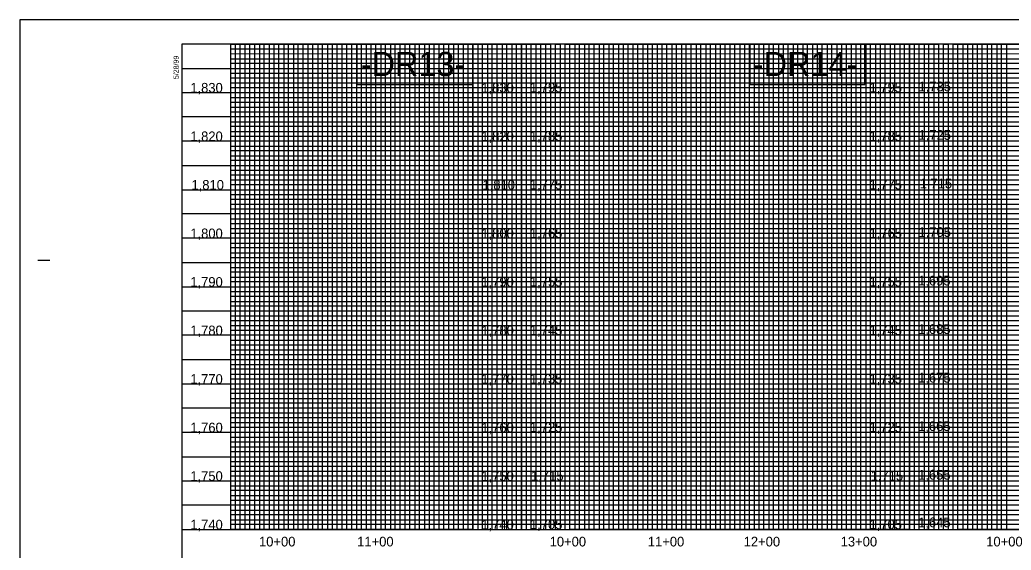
# Model space of a CAD drawing. Extents: x 505602 to 507286, y 483109 to 484209.
# Drawn here: x 505602 to 506624, y 483662 to 484209 of the extents above; entities that cross this region are included whole.
import ezdxf

# ---------------------------------------------------------------- set-up
doc = ezdxf.new("R2010")
doc.units = 0
for name, color, linetype in [('Exist Vertical Profile Vertical Axis Label', 7, 'Continuous'), ('Old_Level_1', 7, 'Continuous'), ('Prop Grid Mask', 7, 'Continuous'), ('Sheet Layout Profile Border Port 1', 7, 'Continuous'), ('Sheet Layout Profile Border Port 2', 7, 'Continuous'), ('Sheet Plot Border Outside CELL', 7, 'Continuous'), ('Sheet Profile CELL', 7, 'Continuous'), ('Sheet Profile Grid Major CELL', 7, 'Continuous'), ('Sheet Profile Grid Middle CELL', 7, 'Continuous'), ('Sheet Profile Grid Minor CELL', 7, 'Continuous')]:
    doc.layers.add(name, color=color, linetype=linetype)

msp = doc.modelspace()

# ---------------------------------------------------------------- linework, layer by layer
at = {"layer": 'Prop Grid Mask'}
for points in [[(506069.1, 484183.7), (505949.5, 484183.7), (505949.5, 484142), (506069.1, 484142)], [(506473.2, 484183.7), (506354.7, 484183.7), (506354.7, 484142), (506473.2, 484142)]]:
    msp.add_lwpolyline(points, close=True, dxfattribs=at)
at = {"layer": 'Sheet Layout Profile Border Port 1'}
msp.add_lwpolyline([(505819.5, 484183.7), (506069.1, 484183.7), (506069.1, 483683.7), (505819.5, 483683.7)], close=True, dxfattribs=at)
at = {"layer": 'Sheet Layout Profile Border Port 2'}
for points in [[(506169.1, 484183.7), (506519.1, 484183.7), (506519.1, 483683.7), (506169.1, 483683.7)], [(506569.1, 484183.7), (507069.1, 484183.7), (507069.1, 483683.7), (506569.1, 483683.7)]]:
    msp.add_lwpolyline(points, close=True, dxfattribs=at)
at = {"layer": 'Sheet Plot Border Outside CELL'}
msp.add_lwpolyline([(505602.1, 483108.7), (507286.1, 483108.7), (507286.1, 484208.7), (505602.1, 484208.7)], close=True, dxfattribs=at)
at = {"layer": 'Sheet Profile CELL'}
for p, q in [((506119.1, 483683.7), (506119.1, 484183.7)), ((506519.1, 483683.7), (506519.1, 484183.7)), ((505620.6, 483961.2), (505633.1, 483961.2)), ((505769.1, 483683.7), (507269.1, 483683.7))]:
    msp.add_line(p, q, dxfattribs=at)
msp.add_lwpolyline([(507269.1, 484183.7), (505769.1, 484183.7), (505769.1, 483133.7), (507269.1, 483133.7)], close=True, dxfattribs=at)
at = {"layer": 'Sheet Profile Grid Major CELL'}
for points in [[(505819.1, 484183.7), (505819.1, 483683.7), (505869.1, 483683.7), (505869.1, 484183.7), (505919.1, 484183.7), (505919.1, 483683.7), (505969.1, 483683.7), (505969.1, 484183.7), (506019.1, 484183.7), (506019.1, 483683.7), (506069.1, 483683.7), (506069.1, 484183.7), (506119.1, 484183.7), (506119.1, 483683.7), (506169.1, 483683.7), (506169.1, 484183.7), (506219.1, 484183.7), (506219.1, 483683.7), (506269.1, 483683.7), (506269.1, 484183.7), (506319.1, 484183.7), (506319.1, 483683.7), (506369.1, 483683.7), (506369.1, 484183.7), (506419.1, 484183.7), (506419.1, 483683.7), (506469.1, 483683.7), (506469.1, 484183.7), (506519.1, 484183.7), (506519.1, 483683.7), (506569.1, 483683.7), (506569.1, 484183.7), (506619.1, 484183.7), (506619.1, 483683.7), (506669.1, 483683.7)], [(505769.1, 484133.7), (507069.1, 484133.7)], [(507069.1, 484083.7), (505769.1, 484083.7), (505769.1, 484033.7), (507069.1, 484033.7)], [(507269.1, 483983.7), (505769.1, 483983.7), (505769.1, 483933.7), (507269.1, 483933.7)], [(507269.1, 483883.7), (505769.1, 483883.7), (505769.1, 483833.7), (507269.1, 483833.7)], [(507269.1, 483783.7), (505769.1, 483783.7), (505769.1, 483783.7), (505769.1, 483733.7), (507269.1, 483733.7)]]:
    msp.add_lwpolyline(points, dxfattribs=at)
at = {"layer": 'Sheet Profile Grid Middle CELL'}
msp.add_line((505769.1, 484158.7), (507069, 484158.7), dxfattribs=at)
msp.add_line((505769.1, 484158.7), (507069, 484158.7), dxfattribs=at)
for points in [[(505844.1, 484183.7), (505844.1, 483683.7), (505894.1, 483683.7), (505894.1, 484183.7), (505944.1, 484183.7), (505944.1, 483683.7), (505994.1, 483683.7), (505994.1, 484183.7), (506044.1, 484183.7), (506044.1, 483683.7), (506094.1, 483683.7), (506094.1, 484183.7), (506144.1, 484183.7), (506144.1, 483683.7), (506194.1, 483683.7), (506194.1, 484183.7), (506244.1, 484183.7), (506244.1, 483683.7), (506294.1, 483683.7), (506294.1, 484183.7), (506344.1, 484183.7), (506344.1, 483683.7), (506394.1, 483683.7), (506394.1, 483683.7), (506394.1, 484183.7), (506444.1, 484183.7), (506444.1, 483683.7), (506494.1, 483683.7), (506494.1, 484183.7), (506544.1, 484183.7), (506544.1, 483683.7), (506594.1, 483683.7), (506594.1, 484183.7), (506644.1, 484183.7)], [(507069.1, 484108.7), (505769.1, 484108.7), (505769.1, 484058.7), (507069.1, 484058.7)], [(507269.1, 484008.7), (505769.1, 484008.7), (505769.1, 483958.7), (507094.1, 483958.7)], [(507269.1, 483908.7), (505769.1, 483908.7), (505769.1, 483858.7), (507269.1, 483858.7)], [(507269.1, 483808.7), (505769.1, 483808.7), (505769.1, 483758.7), (507269.1, 483758.7)], [(507269.1, 483708.7), (505769.1, 483708.7)]]:
    msp.add_lwpolyline(points, dxfattribs=at)
at = {"layer": 'Sheet Profile Grid Minor CELL'}
for p, q in [((505819.1, 484178.7), (507069.1, 484178.7)), ((505819.1, 484173.7), (505819.1, 484173.7)), ((507069.1, 484173.7), (505819.1, 484173.4)), ((505819.1, 484168.7), (507069.1, 484168.7)), ((507069, 484048.7), (505819.1, 484048.7)), ((507069.1, 484043.7), (505819.1, 484043.7)), ((507069.1, 484038.7), (505819.1, 484038.7)), ((505819.1, 484028.7), (507069.1, 484028.7)), ((507069.1, 484023.7), (505819.1, 484023.7)), ((505819.1, 484018.7), (507219.1, 484018.7)), ((507219.1, 483998.7), (505819.1, 483998.7)), ((505819.1, 483993.7), (507219.1, 483993.7)), ((507219.1, 483973.7), (505819.1, 483973.7)), ((505819.1, 483968.7), (507219.1, 483968.7)), ((507219.1, 483948.7), (505819.1, 483948.7)), ((505819.1, 483943.7), (507219.1, 483943.7)), ((507219.1, 483938.7), (505819.1, 483938.7)), ((505819.1, 483928.7), (507219.1, 483928.7)), ((507219.1, 483923.7), (505819.1, 483923.7)), ((505819.1, 483918.7), (507219.1, 483918.7)), ((507219.1, 483913.7), (505819.1, 483913.7)), ((505819.1, 483903.7), (507219.1, 483903.7)), ((507219.1, 483898.7), (505819.1, 483898.7)), ((505819.1, 483893.7), (507219.1, 483893.7)), ((507219.1, 483888.7), (505819.1, 483888.7)), ((505819.1, 483878.7), (507219.1, 483878.7)), ((507219.1, 483873.7), (505819.1, 483873.7)), ((505819.1, 483868.7), (507219.1, 483868.7)), ((507219.1, 483863.7), (505819.1, 483863.7)), ((505819.1, 483853.7), (507219.1, 483853.7)), ((507219.1, 483848.7), (505819.1, 483848.7)), ((505819.1, 483843.7), (507219.1, 483843.7)), ((507219.1, 483838.7), (505819.1, 483838.7)), ((505819.1, 483828.7), (507219.1, 483828.7)), ((507219.1, 483823.7), (505819.1, 483823.7)), ((505819.1, 483818.7), (507219.1, 483818.7)), ((507219.1, 483813.7), (505819.1, 483813.7)), ((505819.1, 483803.7), (507219.1, 483803.7)), ((507219.1, 483798.7), (505819.1, 483798.7)), ((507219.1, 483793.7), (505819.1, 483793.7)), ((507219.1, 483788.7), (505819.1, 483788.7)), ((505819.1, 483778.7), (507219.1, 483778.7)), ((507219.1, 483773.7), (505819.1, 483773.7)), ((505819.1, 483768.7), (507219.1, 483768.7)), ((507219.1, 483763.7), (505819.1, 483763.7)), ((505819.1, 483753.7), (507219.1, 483753.7)), ((507219.1, 483748.7), (505819.1, 483748.7)), ((505819.1, 483743.7), (507219.1, 483743.7)), ((507219.1, 483738.7), (505819.1, 483738.7)), ((505819.1, 483728.7), (507219.1, 483728.7)), ((507219.1, 483723.7), (505819.1, 483723.7)), ((505819.1, 483718.7), (507219.1, 483718.7)), ((507219.1, 483713.7), (505819.1, 483713.7)), ((505819.1, 483703.7), (507219.1, 483703.7)), ((507219.1, 483698.7), (505819.1, 483698.7)), ((505819.1, 483693.7), (507219.1, 483693.7))]:
    msp.add_line(p, q, dxfattribs=at)
for points in [[(505824.1, 484183.7), (505824.1, 483683.7), (505829.1, 483683.7), (505829.1, 484183.7), (505834.1, 484183.7), (505834.1, 483683.7), (505839.1, 483683.7), (505839.1, 484183.7), (505849.1, 484183.7), (505849.1, 483683.7), (505854.1, 483683.7), (505854.1, 484183.7), (505859.1, 484183.7), (505859.1, 483683.7), (505864.1, 483683.7), (505874.1, 483683.7), (505879.1, 483683.7), (505879.1, 484183.7), (505884.1, 484183.7), (505884.1, 483683.7), (505889.1, 483683.7), (505889.1, 484183.7), (505899.1, 484183.7), (505899.1, 483683.7), (505904.1, 483683.7), (505904.1, 484183.7), (505909.1, 484183.7), (505909.1, 483683.7), (505914.1, 483683.7), (505914.1, 484183.7), (505924.1, 484183.7), (505924.1, 483683.7), (505929.1, 483683.7), (505929.1, 484183.7), (505934.1, 484183.7), (505934.1, 483683.7), (505939.1, 483683.7), (505939.1, 484183.7), (505949.1, 484183.7), (505949.1, 483683.7), (505954.1, 483683.7), (505954.1, 484183.7), (505959.1, 484183.7), (505959.1, 483683.7), (505964.1, 483683.7), (505964.1, 484183.7), (505974.1, 484183.7), (505974.1, 483683.7), (505979.1, 483683.7), (505979.1, 484183.7), (505984.1, 484183.7), (505984.1, 483683.7), (505989.1, 483683.7), (505989.1, 484183.7), (505999.1, 484183.7), (505999.1, 483683.7), (506004.1, 483683.7), (506004.1, 484183.7), (506009.1, 484183.7), (506009.1, 483683.7), (506014.1, 483683.7), (506014.1, 484183.7), (506024.1, 484183.7), (506024.1, 483683.7), (506029.1, 483683.7), (506029.1, 484183.7), (506034.1, 484183.7), (506034.1, 483683.7)], [(505864.1, 483683.7), (505864.1, 484183.7), (505874.1, 484183.7), (505874.1, 483683.7)], [(506034.1, 483683.7), (506039.1, 483683.7), (506039.1, 484183.7), (506049.1, 484183.7), (506049.1, 483683.7), (506054.1, 483683.7), (506054.1, 484183.7), (506059.1, 484183.7), (506059.1, 483683.7), (506064.1, 483683.7), (506064.1, 484183.7), (506074.1, 484183.7), (506074.1, 483683.7), (506079.1, 483683.7), (506079.1, 484183.7), (506084.1, 484183.7), (506084.1, 483683.7), (506089.1, 483683.7), (506089.1, 484183.7), (506099.1, 484183.7), (506099.1, 483683.7), (506104.1, 483683.7), (506104.1, 484183.7), (506109.1, 484183.7), (506109.1, 483683.7), (506114.1, 483683.7), (506114.1, 484183.7), (506124.1, 484183.7), (506124.1, 483683.7), (506129.1, 483683.7), (506129.1, 484183.7), (506134.1, 484183.7), (506134.1, 483683.7), (506139.1, 483683.7), (506139.1, 484183.7), (506149.1, 484183.7), (506149.1, 483683.7), (506154.1, 483683.7), (506154.1, 484183.7), (506159.1, 484183.7), (506159.1, 483683.7), (506164.1, 483683.7), (506164.1, 484183.7), (506174.1, 484183.7), (506174.1, 483683.7), (506179.1, 483683.7), (506179.1, 484183.7), (506184.1, 484183.7), (506184.1, 483683.7), (506189.1, 483683.7), (506189.1, 484183.7), (506199.1, 484183.7), (506199.1, 483683.7), (506204.1, 483683.7), (506204.1, 484183.7), (506209.1, 484183.7), (506209.1, 483683.7), (506214.1, 483683.7), (506214.1, 484183.7), (506224.1, 484183.7), (506224.1, 483683.7), (506229.1, 483683.7), (506229.1, 484183.7), (506234.1, 484183.7), (506234.1, 483683.7), (506239.1, 483683.7), (506239.1, 484183.7), (506249.1, 484183.7), (506249.1, 483683.7), (506254.1, 483683.7), (506254.1, 484183.7), (506259.1, 484183.7), (506259.1, 483683.7), (506264.1, 483683.7), (506264.1, 484183.7), (506274.1, 484183.7), (506274.1, 483683.7), (506279.1, 483683.7), (506279.1, 484183.7), (506284.1, 484183.7), (506284.1, 483683.7), (506289.1, 483683.7), (506289.1, 484183.7), (506299.1, 484183.7), (506299.1, 483683.7), (506304.1, 483683.7), (506304.1, 484183.7), (506309.1, 484183.7), (506309.1, 483683.7), (506314.1, 483683.7), (506314.1, 484183.7), (506324.1, 484183.7), (506324.1, 483683.7), (506329.1, 483683.7), (506329.1, 484183.7), (506334.1, 484183.7), (506334.1, 483683.7), (506339.1, 483683.7), (506339.1, 484183.7), (506349.1, 484183.7)], [(506349.1, 484183.7), (506349.1, 483683.7), (506354.1, 483683.7), (506354.1, 484183.7), (506359.1, 484183.7), (506359.1, 483683.7), (506364.1, 483683.7), (506364.1, 484183.7), (506374.1, 484183.7), (506374.1, 483683.7), (506379.1, 483683.7), (506379.1, 484183.7), (506384.1, 484183.7), (506384.1, 483683.7), (506389.1, 483683.7), (506389.1, 484183.7), (506399.1, 484183.7), (506399.1, 483683.7), (506404.1, 483683.7), (506404.1, 484183.7), (506409.1, 484183.7), (506409.1, 483683.7), (506414.1, 483683.7), (506414.1, 484183.7), (506424.1, 484183.7), (506424.1, 483683.7), (506429.1, 483683.7), (506429.1, 484183.7), (506434.1, 484183.7), (506434.1, 483683.7), (506439.1, 483683.7), (506439.1, 484183.7), (506449.1, 484183.7), (506449.1, 483683.7), (506454.1, 483683.7), (506454.1, 484183.7), (506459.1, 484183.7), (506459.1, 483683.7), (506464.1, 483683.7), (506464.1, 484183.7), (506474.1, 484183.7), (506474.1, 483683.7), (506474.1, 483683.7), (506479.1, 483683.7), (506479.1, 484183.7), (506484.1, 484183.7), (506484.1, 483683.7), (506489.1, 483683.7), (506489.1, 484183.7), (506499.1, 484183.7), (506499.1, 483683.7), (506504.1, 483683.7), (506504.1, 484183.7), (506509.1, 484183.7), (506509.1, 483683.7), (506514.1, 483683.7), (506514.1, 484183.7), (506524.1, 484183.7), (506524.1, 483683.7), (506529.1, 483683.7), (506529.1, 484183.7), (506534.1, 484183.7), (506534.1, 483683.7), (506539.1, 483683.7), (506539.1, 484183.7), (506549.1, 484183.7), (506549.1, 483683.7), (506554.1, 483683.7), (506554.1, 484183.7), (506559.1, 484183.7), (506559.1, 483683.7), (506564.1, 483683.7), (506564.1, 484183.7), (506574.1, 484183.7), (506574.1, 483683.7), (506579.1, 483683.7), (506579.1, 484183.7), (506584.1, 484183.7), (506584.1, 483683.7), (506589.1, 483683.7), (506589.1, 484183.7), (506599.1, 484183.7), (506599.1, 483683.7), (506604.1, 483683.7), (506604.1, 484183.7), (506609.1, 484183.7), (506609.1, 483683.7), (506614.1, 483683.7), (506614.1, 484183.7), (506624.1, 484183.7)], [(507069.1, 484163.7), (505819.1, 484163.7), (505819.1, 484153.7), (507069.1, 484153.7)], [(507069, 484148.7), (505819.1, 484148.7), (505819.1, 484143.7), (507069.1, 484143.7)], [(507069.1, 484138.7), (505819.1, 484138.7), (505819.1, 484128.7), (507069.1, 484128.7)], [(507069.1, 484123.7), (505819.1, 484123.7), (505819.1, 484118.7), (507069.1, 484118.7)], [(507069.1, 484113.7), (505819.1, 484113.7), (505819.1, 484103.7), (507069.1, 484103.7)], [(507069.1, 484098.7), (505819.1, 484098.7), (505819.1, 484093.7), (507069.1, 484093.7)], [(507069.1, 484088.7), (505819.1, 484088.7), (505819.1, 484078.7), (507069.1, 484078.7)], [(507069.1, 484073.6), (505819.2, 484073.6), (505819.2, 484068.7), (507069.1, 484068.7)], [(507069.1, 484063.7), (505819.1, 484063.7), (505819.1, 484053.7), (507069.1, 484053.7)], [(507219.1, 484013.7), (505819.1, 484013.7), (505819.1, 484003.7), (507219.1, 484003.7)], [(507219.1, 483988.7), (505819.1, 483988.7), (505819.1, 483978.7), (507219.1, 483978.7)], [(507219.1, 483963.7), (505819.1, 483963.7), (505819.1, 483953.7), (507219.1, 483953.7)], [(507219.1, 483688.7), (505819.1, 483688.7)]]:
    msp.add_lwpolyline(points, dxfattribs=at)

# ---------------------------------------------------------------- texts
at = {"layer": 'Exist Vertical Profile Vertical Axis Label'}
for s, p in [('1,830', (505777.8, 484133.7)), ('1,830', (506077.8, 484133.7)), ('1,795', (506127.9, 484134)), ('1,795', (506477.9, 484134)), ('1,735', (506528.4, 484135.1)), ('1,725', (506528.4, 484085.1)), ('1,820', (505777.8, 484083.7)), ('1,820', (506077.8, 484083.7)), ('1,785', (506127.9, 484084)), ('1,785', (506477.9, 484084)), ('1,810', (505779, 484033.7)), ('1,810', (506079, 484033.7)), ('1,775', (506127.9, 484034)), ('1,775', (506477.9, 484034)), ('1,715', (506529.6, 484035.1)), ('1,800', (505777.8, 483983.7)), ('1,800', (506077.8, 483983.7)), ('1,765', (506127.9, 483984)), ('1,765', (506477.9, 483984)), ('1,705', (506528.4, 483985.1)), ('1,790', (505777.8, 483933.7)), ('1,790', (506077.8, 483933.7)), ('1,755', (506127.9, 483934)), ('1,755', (506477.9, 483934)), ('1,695', (506528, 483935.1)), ('1,780', (505777.8, 483883.7)), ('1,780', (506077.8, 483883.7)), ('1,745', (506127.9, 483884)), ('1,745', (506477.9, 483884)), ('1,685', (506528, 483885.1)), ('1,770', (505777.8, 483833.7)), ('1,770', (506077.8, 483833.7)), ('1,735', (506127.9, 483834)), ('1,735', (506477.9, 483834)), ('1,675', (506528, 483835.1)), ('1,760', (505777.8, 483783.7)), ('1,760', (506077.8, 483783.7)), ('1,725', (506127.9, 483784)), ('1,725', (506477.9, 483784)), ('1,665', (506528, 483785.1)), ('1,750', (505777.8, 483733.7)), ('1,750', (506077.8, 483733.7)), ('1,715', (506129.1, 483734)), ('1,715', (506479.1, 483734)), ('1,655', (506528, 483735.1)), ('1,740', (505777.8, 483683.7)), ('1,740', (506077.8, 483683.7)), ('1,705', (506127.9, 483684)), ('1,705', (506477.9, 483684)), ('1,645', (506528, 483686)), ('10+00', (505848.6, 483666.2)), ('11+00', (505949.8, 483666.2)), ('10+00', (506148.2, 483666.2)), ('11+00', (506249.4, 483666.2)), ('12+00', (506348.2, 483666.2)), ('13+00', (506448.2, 483666.2)), ('10+00', (506598.2, 483666.2))]:
    msp.add_text(s, height=10, dxfattribs=at).set_placement(p)
at = {"layer": 'Old_Level_1'}
for s, p in [('-DR13-', (505953.5, 484150.7)), ('-DR14-', (506357.6, 484150.7))]:
    msp.add_text(s, height=25, dxfattribs=at).set_placement(p)
at = {"layer": 'Sheet Profile CELL'}
msp.add_text('5/28/99', height=5.25, rotation=90, dxfattribs=at).set_placement((505765.8, 484147.6))

doc.saveas('drawing.dxf')
